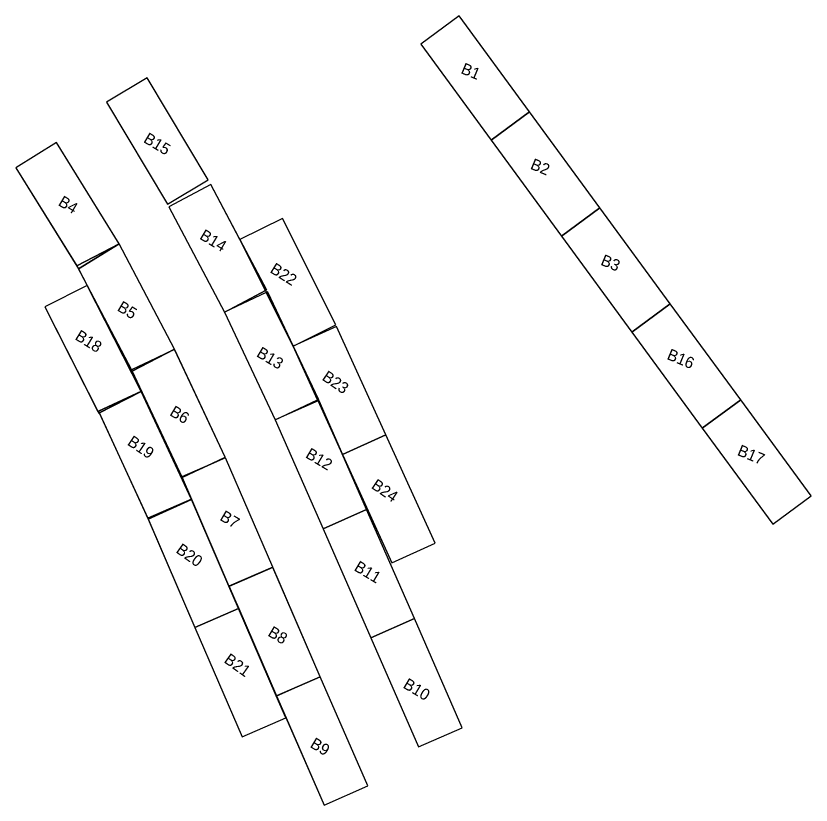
# Model space of a CAD drawing. Extents: x 511719 to 511886, y 6211766 to 6211932.
import ezdxf

# ---------------------------------------------------------------- set-up
doc = ezdxf.new("R2010")
doc.units = 0
for name, color, linetype in [('Default', 7, 'Continuous'), ('TV_P_BEF_BaerL', 7, 'Continuous'), ('TV_U_APT_RakVk', 7, 'Continuous')]:
    doc.layers.add(name, color=color, linetype=linetype)

msp = doc.modelspace()

# ---------------------------------------------------------------- linework, layer by layer
at = {"layer": 'TV_P_BEF_BaerL'}
for p, q in [((511732.12, 6211879.29), (511740.98, 6211883.94)), ((511740.98, 6211883.94), (511732.48, 6211878.67)), ((511752.59, 6211861.8), (511740.98, 6211883.94)), ((511771.68, 6211874.12), (511766.35, 6211884.8)), ((511771.68, 6211874.12), (511771.87, 6211873.73)), ((511777.51, 6211862.44), (511771.87, 6211873.73)), ((511856.72, 6211871.3), (511848.66, 6211865.39)), ((511848.66, 6211865.39), (511856.72, 6211871.3)), ((511871.5, 6211851.14), (511856.72, 6211871.3)), ((511848.66, 6211865.39), (511863.43, 6211845.23)), ((511743.56, 6211857.48), (511752.59, 6211861.8)), ((511752.59, 6211861.8), (511743.73, 6211857.15)), ((511782.64, 6211851.17), (511777.51, 6211862.44)), ((511736.61, 6211848.76), (511745.61, 6211852.91)), ((511745.61, 6211852.91), (511736.77, 6211848.41)), ((511756.16, 6211830.25), (511745.61, 6211852.91)), ((511782.64, 6211851.17), (511782.76, 6211850.91)), ((511787.87, 6211839.68), (511782.76, 6211850.91)), ((511863.43, 6211845.23), (511871.5, 6211851.14)), ((511871.5, 6211851.14), (511863.43, 6211845.23)), ((511863.43, 6211845.23), (511878.21, 6211825.06)), ((511787.87, 6211839.68), (511796.97, 6211843.82)), ((511796.97, 6211843.82), (511787.87, 6211839.68)), ((511787.94, 6211839.53), (511787.87, 6211839.68)), ((511787.94, 6211839.53), (511798.23, 6211816.93)), ((511754.13, 6211834.99), (511758.4, 6211836.83)), ((511758.4, 6211836.83), (511754.19, 6211834.86)), ((511746.99, 6211826.3), (511756.16, 6211830.25)), ((511756.16, 6211830.25), (511747.09, 6211826.06)), ((511793.82, 6211801.17), (511802.98, 6211805.19)), ((511802.98, 6211805.19), (511793.82, 6211801.17)), ((511783.17, 6211792.98), (511773.99, 6211789.01)), ((511773.99, 6211789.01), (511783.17, 6211792.98))]:
    msp.add_line(p, q, dxfattribs=at)
for points in [[(511819.1, 6211905.72), (511827.16, 6211911.63), (511812.38, 6211931.79), (511804.32, 6211925.88), (511819.1, 6211905.72)], [(511751.12, 6211892.23), (511759.7, 6211897.36), (511746.89, 6211918.82), (511738.3, 6211913.69), (511751.12, 6211892.23)], [(511833.88, 6211885.56), (511841.94, 6211891.47), (511827.16, 6211911.63), (511819.1, 6211905.72), (511833.88, 6211885.56)], [(511740.98, 6211883.94), (511727.8, 6211905.18), (511719.3, 6211899.91), (511732.1, 6211879.28)], [(511766.35, 6211884.8), (511760.25, 6211896.35), (511751.41, 6211891.68), (511763.08, 6211869.58), (511771.68, 6211874.12)], [(511856.72, 6211871.3), (511841.94, 6211891.47), (511833.88, 6211885.56), (511848.66, 6211865.39)], [(511777.52, 6211862.44), (511786.46, 6211866.9), (511775.3, 6211889.27), (511766.35, 6211884.8)], [(511766.35, 6211884.8), (511771.92, 6211874.25), (511771.68, 6211874.12)], [(511732.1, 6211879.28), (511732.12, 6211879.29)], [(511732.48, 6211878.67), (511732.46, 6211878.65)], [(511732.46, 6211878.65), (511734.27, 6211875.19), (511743.56, 6211857.48)], [(511745.61, 6211852.91), (511734.27, 6211875.19), (511725.36, 6211870.66), (511736.52, 6211848.71)], [(511771.87, 6211873.73), (511763.08, 6211869.58), (511773.76, 6211846.97), (511782.64, 6211851.17)], [(511771.87, 6211873.73), (511772.12, 6211873.85), (511777.52, 6211862.44)], [(511796.97, 6211843.82), (511786.62, 6211866.58), (511777.52, 6211862.44)], [(511758.4, 6211836.83), (511763.24, 6211839.11), (511752.59, 6211861.8)], [(511777.52, 6211862.44), (511782.81, 6211851.25), (511782.64, 6211851.17)], [(511743.56, 6211857.48), (511743.56, 6211857.48)], [(511743.73, 6211857.15), (511743.72, 6211857.15)], [(511743.72, 6211857.15), (511745.69, 6211852.95), (511754.13, 6211834.99)], [(511782.76, 6211850.91), (511773.76, 6211846.97), (511783.79, 6211824.07), (511792.95, 6211828.09), (511787.94, 6211839.53)], [(511782.76, 6211850.91), (511782.92, 6211850.99), (511787.87, 6211839.68)], [(511878.21, 6211825.06), (511886.28, 6211830.98), (511871.5, 6211851.14)], [(511736.52, 6211848.71), (511736.61, 6211848.76)], [(511736.77, 6211848.41), (511736.77, 6211848.41), (511746.98, 6211826.29)], [(511798.23, 6211816.93), (511807.33, 6211821.07), (511796.97, 6211843.82)], [(511764.04, 6211812.04), (511773.22, 6211816), (511763.31, 6211838.95), (511758.4, 6211836.83)], [(511787.87, 6211839.68), (511787.87, 6211839.68), (511787.94, 6211839.53)], [(511754.13, 6211834.99), (511754.13, 6211834.99)], [(511754.19, 6211834.86), (511754.19, 6211834.86), (511756.18, 6211830.26), (511764.04, 6211812.04)], [(511756.89, 6211803.34), (511766.07, 6211807.3), (511764.03, 6211812.03), (511756.16, 6211830.25)], [(511802.98, 6211805.19), (511792.95, 6211828.09), (511783.79, 6211824.07), (511793.82, 6211801.17)], [(511746.98, 6211826.29), (511746.99, 6211826.3)], [(511747.09, 6211826.06), (511747.09, 6211826.06), (511756.89, 6211803.34)], [(511783.17, 6211792.98), (511773.22, 6211816), (511764.04, 6211812.04), (511766.09, 6211807.3), (511773.99, 6211789.01)], [(511766.07, 6211807.3), (511756.89, 6211803.34), (511766.79, 6211780.38), (511775.98, 6211784.34), (511773.97, 6211789), (511766.07, 6211807.3)], [(511793.82, 6211801.17), (511803.85, 6211778.27), (511813.01, 6211782.28), (511802.98, 6211805.19)], [(511784.04, 6211766.03), (511793.2, 6211770.04), (511783.17, 6211792.98)], [(511773.99, 6211789.01), (511776.02, 6211784.36), (511784.04, 6211766.03)]]:
    msp.add_lwpolyline(points, dxfattribs=at)
at = {"layer": 'TV_U_APT_RakVk'}
for points in [[(511819.1, 6211905.72), (511827.16, 6211911.63), (511812.38, 6211931.79), (511804.32, 6211925.88)], [(511751.12, 6211892.23), (511759.7, 6211897.36), (511746.89, 6211918.82), (511738.3, 6211913.69)], [(511833.88, 6211885.56), (511841.94, 6211891.47), (511827.16, 6211911.63), (511819.1, 6211905.72)], [(511732.48, 6211878.67), (511740.98, 6211883.94), (511727.8, 6211905.18), (511719.3, 6211899.91)], [(511763.08, 6211869.58), (511771.92, 6211874.25), (511760.25, 6211896.35), (511751.41, 6211891.68)], [(511848.66, 6211865.39), (511856.72, 6211871.3), (511841.94, 6211891.47), (511833.88, 6211885.56)], [(511777.51, 6211862.44), (511786.46, 6211866.9), (511775.3, 6211889.27), (511766.35, 6211884.8)], [(511743.73, 6211857.15), (511752.59, 6211861.8), (511740.98, 6211883.94), (511732.12, 6211879.29)], [(511736.69, 6211848.37), (511745.61, 6211852.91), (511734.27, 6211875.19), (511725.36, 6211870.66)], [(511773.76, 6211846.97), (511782.81, 6211851.25), (511772.12, 6211873.85), (511763.08, 6211869.58)], [(511863.43, 6211845.23), (511871.5, 6211851.14), (511856.72, 6211871.3), (511848.66, 6211865.39)], [(511787.87, 6211839.68), (511796.97, 6211843.82), (511786.62, 6211866.58), (511777.52, 6211862.44)], [(511754.19, 6211834.86), (511763.24, 6211839.11), (511752.61, 6211861.74), (511743.56, 6211857.48)], [(511747.08, 6211826.06), (511756.16, 6211830.25), (511745.69, 6211852.95), (511736.61, 6211848.76)], [(511783.79, 6211824.07), (511792.95, 6211828.09), (511782.92, 6211850.99), (511773.76, 6211846.97)], [(511878.21, 6211825.06), (511886.28, 6211830.98), (511871.5, 6211851.14), (511863.43, 6211845.23)], [(511798.23, 6211816.93), (511807.33, 6211821.07), (511796.97, 6211843.82), (511787.87, 6211839.68)], [(511764.04, 6211812.04), (511773.22, 6211816), (511763.31, 6211838.95), (511754.13, 6211834.99)], [(511756.89, 6211803.34), (511766.07, 6211807.3), (511756.18, 6211830.26), (511746.99, 6211826.3)], [(511793.82, 6211801.17), (511802.98, 6211805.19), (511792.95, 6211828.09), (511783.79, 6211824.07)], [(511773.99, 6211789.01), (511783.17, 6211792.98), (511773.25, 6211815.93), (511764.07, 6211811.96)], [(511766.79, 6211780.38), (511775.98, 6211784.34), (511766.08, 6211807.3), (511756.9, 6211803.34)], [(511803.85, 6211778.27), (511813.01, 6211782.28), (511802.98, 6211805.19), (511793.82, 6211801.17)], [(511784.04, 6211766.03), (511793.2, 6211770.04), (511783.18, 6211792.94), (511774.02, 6211788.93)]]:
    msp.add_lwpolyline(points, close=True, dxfattribs=at)

# ---------------------------------------------------------------- texts
at = {"layer": 'Default'}
for s, rotation, p in [('B1', 337.5159, (511812.57, 6211919.81)), ('B15', 329.1142, (511745.91, 6211905.36)), ('B2', 337.5159, (511827.15, 6211899.73)), ('B4', 329.1142, (511728, 6211892.11)), ('B14', 329.1142, (511757.69, 6211885.06)), ('B3', 337.5159, (511841.91, 6211879.57)), ('B22', 327.8035, (511772.48, 6211878.04)), ('B5', 329.1142, (511740.4, 6211870)), ('B18', 328.2382, (511731.53, 6211863.95)), ('B13', 329.1142, (511769.64, 6211860.37)), ('B16', 337.5159, (511855.83, 6211859.76)), ('B23', 325.7419, (511783.4, 6211855.46)), ('B6', 329.1142, (511751.4, 6211848.01)), ('B19', 326.0442, (511742.52, 6211841.82)), ('B17', 337.5159, (511870.61, 6211839.6)), ('B12', 329.1142, (511779.93, 6211839.14)), ('B24', 325.7419, (511793.75, 6211832.71)), ('B7', 329.1142, (511761.94, 6211826.01)), ('B20', 324.5898, (511752.73, 6211819.21)), ('B11', 329.1142, (511790.13, 6211815.42)), ('B8', 329.1142, (511772.02, 6211801.7)), ('B21', 324.5898, (511762.82, 6211796.12)), ('B10', 329.1142, (511800.41, 6211790.78)), ('B9', 329.1142, (511780.89, 6211778.29))]:
    msp.add_text(s, height=2.4, rotation=rotation, dxfattribs=at).set_placement(p)

doc.saveas('drawing.dxf')
